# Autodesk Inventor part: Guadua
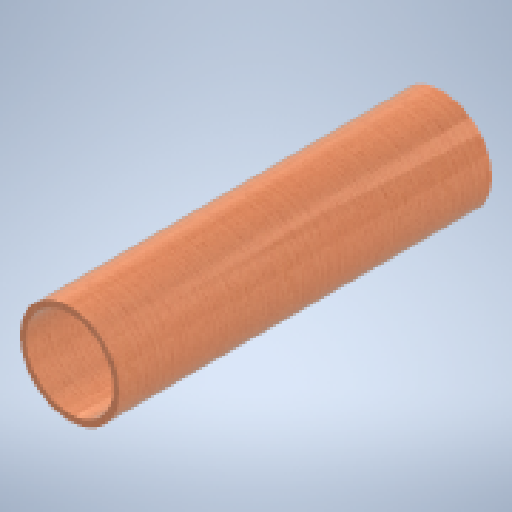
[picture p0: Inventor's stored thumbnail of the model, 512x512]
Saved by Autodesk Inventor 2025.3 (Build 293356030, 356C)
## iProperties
Created: 2025-09
Part Number: Guadua
Material: Genérico
Document SubType Name: Modeling
Designer: User
Density: 1 g/cm^3
Appearance: Valor por defecto
Author: User
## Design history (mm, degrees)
sketch "Boceto1"
  geometry: C1 r 80 at (0, 0); 1 further point
  constraints: 1 centre point, 1 coincident
  dimensions: "d0" = 160 diameter of C1
extrude "Extrusión1" new body sketch "Boceto1" distance "d1" = 600; taper "d2" = 0 deg
sketch "Boceto2"
  geometry: 2 further points
  constraints: 1 coincident
hole "Agujero1" sketch "Boceto2" at (0, 0) diameter "d3" = 140; stored, may be unused: countersink angle "d7" = 90 deg, drill point angle "d9" = 0 deg; dims "d4" = 6, "d5" = 4, "d6" = 2, "d8" = 31.296
node "Sólido1"
node "Acabados"
node "Finish4" dims "Finish4_Area" = 57491.14556
